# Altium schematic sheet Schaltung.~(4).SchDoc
size A4
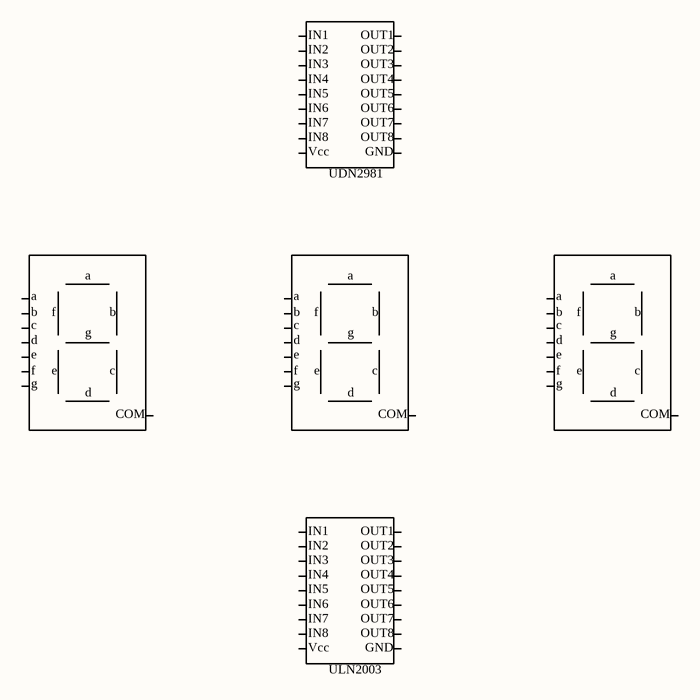
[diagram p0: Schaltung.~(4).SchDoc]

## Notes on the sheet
- IN1
- IN2
- IN3
- IN4
- OUT1
- OUT2
- OUT3
- OUT4
- IN5
- IN6
- IN7
- IN8
- Vcc
- OUT5
- OUT6
- OUT7
- OUT8
- GND
- UDN2981
- a
- b
- f
- c
- d
- e
- g
- COM
- ULN2003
